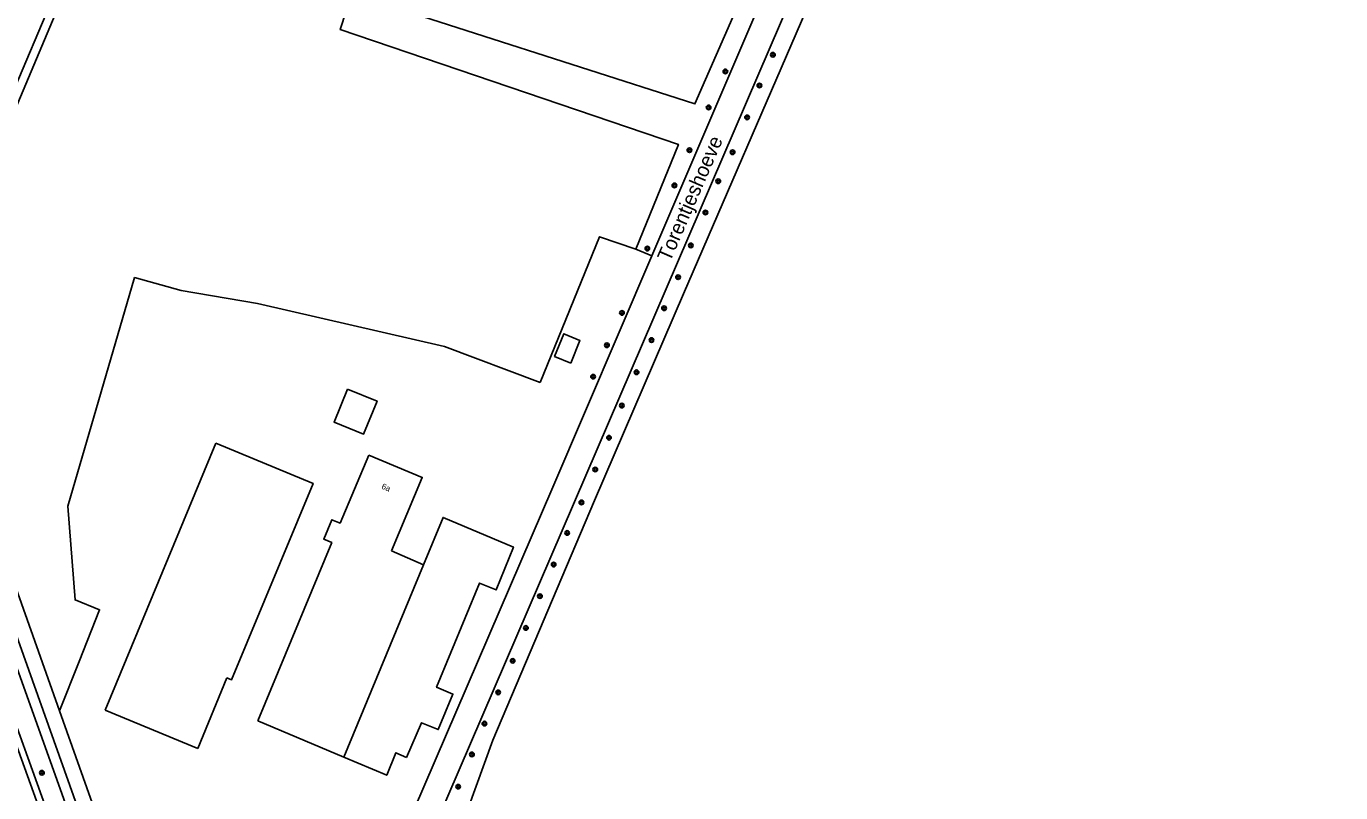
# Model space of a CAD drawing. Extents: x 135990 to 139000, y 393500 to 396000.
# Drawn here: x 136534.3 to 136760.9, y 394858.8 to 394991 of the extents above; entities that cross this region are included whole.
import ezdxf

# ---------------------------------------------------------------- set-up
doc = ezdxf.new("R2010")
doc.units = 0
for name, color, linetype in [('gg-anno-huisnummerreeks BGT', 7, 'Continuous'), ('gg-anno-openbare ruimte label', 7, 'Continuous'), ('gg-bbg-bijgebouw', 7, 'Continuous'), ('gg-bbg-hoofdgebouw', 7, 'Continuous'), ('gg-bbg-tussenscheiding', 7, 'Continuous'), ('gg-knt-bronhoudergrens', 7, 'Continuous'), ('gg-knt-onverhard', 7, 'Continuous'), ('gg-knt-verharding', 7, 'Continuous'), ('gg-kntw-bovenkant insteek waterloop', 7, 'Continuous'), ('gt-grn-groengrens', 7, 'Continuous'), ('gt-symb-boom', 7, 'Continuous'), ('gx-grn-maaiveld', 7, 'Continuous')]:
    doc.layers.add(name, color=color, linetype=linetype)

# ---------------------------------------------------------------- blocks, each defined once
blk = doc.blocks.new('gt0-BOOM')
at = {"layer": 'gt-symb-boom'}
for radius in [0.4, 0.2]:
    blk.add_circle((0, 0), radius, dxfattribs=at)

msp = doc.modelspace()

# ---------------------------------------------------------------- linework, layer by layer
at = {"layer": 'gg-bbg-bijgebouw'}
for p, q in [((136566.98, 394919.09), (136547.928, 394873.066)), ((136568.863, 394878.65), (136563.852, 394866.474)), ((136547.928, 394873.066), (136563.852, 394866.474))]:
    msp.add_line(p, q, dxfattribs=at)
for points in [[(136628.167, 394932.888), (136625.402, 394934.044), (136627.001, 394937.947), (136629.766, 394936.79), (136628.167, 394932.888)], [(136589.68, 394928.428), (136594.78, 394926.347), (136592.462, 394920.642), (136587.362, 394922.723), (136589.68, 394928.428)], [(136566.98, 394919.09), (136583.754, 394912.146), (136569.686, 394878.308), (136568.863, 394878.65)], [(136602.788, 394898.129), (136606.16, 394906.3), (136618.302, 394901.179), (136615.317, 394893.794), (136612.469, 394894.965), (136605.031, 394877.014), (136607.864, 394875.827), (136605.327, 394869.722), (136602.456, 394870.897), (136599.872, 394864.875)], [(136599.872, 394864.875), (136598.027, 394865.731), (136596.457, 394861.828), (136589.028, 394864.969)]]:
    msp.add_lwpolyline(points, dxfattribs=at)
at = {"layer": 'gg-bbg-hoofdgebouw'}
for p, q in [((136597.263, 394900.508), (136602.788, 394898.129)), ((136589.028, 394864.969), (136574.235, 394871.224))]:
    msp.add_line(p, q, dxfattribs=at)
for points in [[(136574.235, 394871.224), (136586.981, 394901.941), (136585.588, 394902.525), (136587, 394905.89), (136588.397, 394905.309), (136593.362, 394917.043)], [(136593.362, 394917.043), (136602.566, 394913.196), (136597.263, 394900.508)]]:
    msp.add_lwpolyline(points, dxfattribs=at)
at = {"layer": 'gg-bbg-tussenscheiding'}
msp.add_line((136602.788, 394898.129), (136589.028, 394864.969), dxfattribs=at)
at = {"layer": 'gg-knt-bronhoudergrens'}
for points in [[(136639.426, 394952.559), (136646.75, 394970.593), (136588.436, 394990.384), (136590.447, 394996.628), (136649.589, 394977.583), (136677.804, 395042.02), (136710.699, 395119.951)], [(136639.426, 394952.559), (136633.143, 394954.685), (136622.913, 394929.55)], [(136540.027, 394872.959), (136543.413, 394881.472), (136546.952, 394890.37), (136542.716, 394892.055), (136541.453, 394908.25), (136552.982, 394947.627), (136561.015, 394945.436), (136574.149, 394943.182), (136606.428, 394935.774), (136622.913, 394929.55)]]:
    msp.add_lwpolyline(points, dxfattribs=at)
at = {"layer": 'gg-knt-onverhard'}
for p, q in [((136667.998, 395000), (136604.63, 394852.754)), ((136662.97, 395000), (136642.156, 394951.39))]:
    msp.add_line(p, q, dxfattribs=at)
msp.add_lwpolyline([(136642.156, 394951.39), (136625.08, 394911.51), (136599.268, 394851.577)], dxfattribs=at)
at = {"layer": 'gg-knt-verharding'}
for p, q in [((136668.79, 394500), (136502.742, 394964.003)), ((136569.294, 394768.782), (136506.374, 394942.942))]:
    msp.add_line(p, q, dxfattribs=at)
msp.add_lwpolyline([(136505.512, 394942.077), (136518.6, 394905.816), (136568.296, 394767.811)], dxfattribs=at)
at = {"layer": 'gg-kntw-bovenkant insteek waterloop'}
msp.add_line((136525.584, 394913.655), (136540.027, 394872.959), dxfattribs=at)
for points in [[(136543.563, 395003.296), (136528.045, 394966.394), (136526.677, 394963.141), (136525.553, 394963.614), (136528.301, 394971.008), (136542.325, 395004.007)], [(136523.02, 394912.745), (136554.12, 394825.49), (136615.21, 394658.072), (136661.88, 394543.88), (136670.581, 394520.988), (136678.884, 394500)], [(136540.027, 394872.959), (136557.26, 394824.404), (136571.312, 394786.266)]]:
    msp.add_lwpolyline(points, dxfattribs=at)
at = {"layer": 'gt-grn-groengrens'}
msp.add_line((136642.156, 394951.39), (136639.426, 394952.559), dxfattribs=at)
at = {"layer": 'gx-grn-maaiveld'}
msp.add_lwpolyline([(136668.727, 394993.566), (136647.643, 394944.812), (136632.295, 394909.177), (136614.716, 394867.912), (136610.414, 394855.963), (136611.452, 394852.998), (136613.194, 394848.106), (136803.297, 394782.302), (136858, 394763.98), (136859.984, 394771.52), (136860.844, 394776.746), (136931.223, 394932.585), (136930.562, 394939.068), (136925.667, 394946.608), (136865.066, 394969.705), (136898.535, 395048.306)], dxfattribs=at)

# ---------------------------------------------------------------- block references
at = {"layer": 'gt-symb-boom'}
for p in [(136663.03, 394986.046), (136654.832, 394983.187), (136660.704, 394980.753), (136651.951, 394976.983), (136658.57, 394975.262), (136648.642, 394969.601), (136656.084, 394969.235), (136646.041, 394963.534), (136653.61, 394964.251), (136651.389, 394958.86), (136641.381, 394952.627), (136648.881, 394953.188), (136646.676, 394947.704), (136644.259, 394942.341), (136637.008, 394941.546), (136634.405, 394935.973), (136642.094, 394936.864), (136639.519, 394931.306), (136632.024, 394930.553), (136636.983, 394925.569), (136634.771, 394920.035), (136632.41, 394914.551), (136630.013, 394908.866), (136627.561, 394903.605), (136625.23, 394898.152), (136622.861, 394892.715), (136620.455, 394887.228), (136618.162, 394881.565), (136615.66, 394876.129), (136613.294, 394870.735), (136611.129, 394865.43), (136536.994, 394862.275), (136608.767, 394859.871)]:
    msp.add_blockref('gt0-BOOM', p, dxfattribs=at)

# ---------------------------------------------------------------- texts
at = {"layer": 'gg-anno-huisnummerreeks BGT'}
msp.add_text('6a', height=1, rotation=337.3, dxfattribs=at).set_placement((136595.47, 394911.285))
at = {"layer": 'gg-anno-openbare ruimte label'}
msp.add_text('Torentjeshoeve', height=2.5, rotation=66.6, dxfattribs=at).set_placement((136645.3, 394950.219))

doc.saveas('drawing.dxf')
